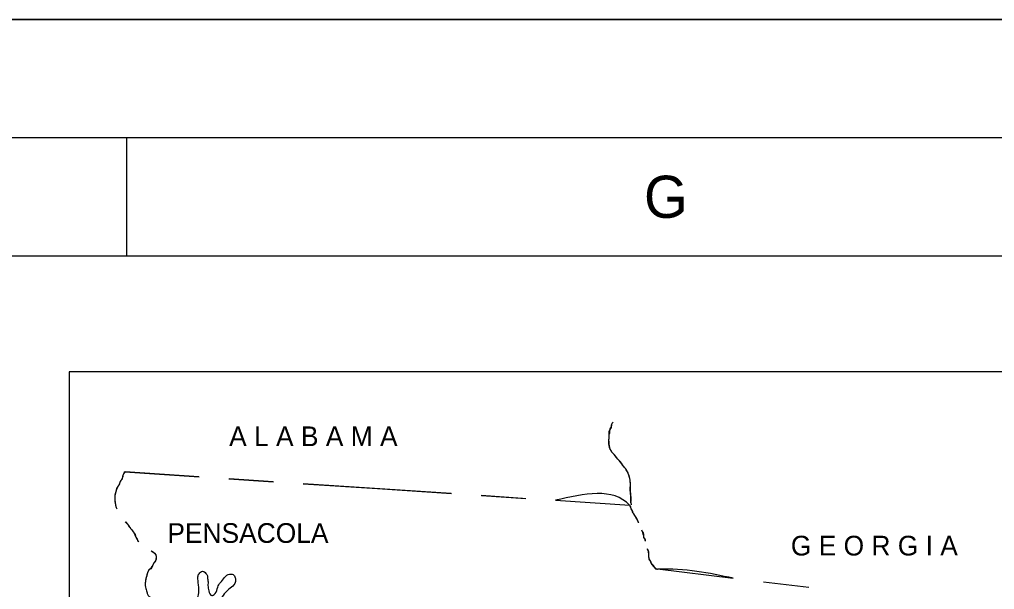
# Model space of a CAD drawing. Extents: x 492225 to 553725, y 1303773 to 1347273.
# Drawn here: x 534669 to 540852, y 1343657 to 1347273 of the extents above; entities that cross this region are included whole.
import ezdxf

# ---------------------------------------------------------------- set-up
doc = ezdxf.new("R2010")
doc.units = 0
for name, color, linetype in [('G-ANNO-TTLB', 7, 'Continuous'), ('Level 62', 7, 'Continuous'), ('Level 63', 7, 'Continuous')]:
    doc.layers.add(name, color=color, linetype=linetype)

msp = doc.modelspace()

# ---------------------------------------------------------------- linework, layer by layer
at = {"layer": 'G-ANNO-TTLB'}
for p, q in [((552975.069, 1346522.564), (492975.069, 1346522.564)), ((535350.069, 1345772.564), (535350.069, 1346522.564)), ((494850.069, 1345772.564), (552225.069, 1345772.564))]:
    msp.add_line(p, q, dxfattribs=at)
for points in [[(492225.069, 1303772.564), (553725.069, 1303772.564), (553725.069, 1347272.564), (492225.069, 1347272.564)], [(492225.069, 1303772.564), (553725.069, 1303772.564), (553725.069, 1347272.564), (492225.069, 1347272.564)], [(492225.069, 1347272.564), (553725.069, 1347272.564), (553725.069, 1303772.564), (492225.069, 1303772.564)]]:
    msp.add_lwpolyline(points, close=True, dxfattribs=at)
at = {"layer": 'Level 63'}
for p, q in [((535806.897, 1344371.438), (535338.382, 1344402.8405)), ((536277.1645, 1344340.028), (535999.0745, 1344359.173)), ((537406.5795, 1344266.3705), (536468.097, 1344327.7405)), ((537858.9745, 1344234.463), (537597.647, 1344253.413)), ((539674.507, 1343668.4205), (539386.667, 1343702.5305))]:
    msp.add_line(p, q, dxfattribs=at)
msp.add_lwpolyline([(534984.2995, 1333099.493), (548263.6245, 1333099.498), (548263.6245, 1345038.098), (534984.2995, 1345038.093)], close=True, dxfattribs=at)
for points in [[(535337.812, 1344402.5055), (535327.812, 1344391.2555), (535321.562, 1344372.5055), (535319.062, 1344357.5055), (535311.562, 1344347.5055), (535306.562, 1344342.5055), (535304.062, 1344330.0055), (535296.562, 1344315.0055), (535291.562, 1344310.0055), (535284.062, 1344291.2555), (535276.562, 1344263.7555), (535274.062, 1344248.7555), (535274.062, 1344216.2555), (535276.562, 1344201.2555), (535282.812, 1344177.5055), (535286.562, 1344167.5055)], [(535336.562, 1344402.5055), (535807.812, 1344371.2555)], [(535996.562, 1344358.7555), (536279.062, 1344340.0055)], [(536467.812, 1344327.5055), (536939.062, 1344297.5055)], [(536939.062, 1344297.5055), (537409.062, 1344266.2555)], [(537597.812, 1344253.7555), (537880.312, 1344235.0055)], [(538069.062, 1344222.5055), (538540.312, 1344191.2555)], [(538595.312, 1344078.7555), (538594.062, 1344081.2555), (538591.562, 1344088.7555), (538565.312, 1344136.2555), (538560.312, 1344141.2555), (538555.312, 1344156.2555), (538547.812, 1344168.7555), (538540.312, 1344191.2555)], [(535341.562, 1344085.0055), (535356.562, 1344070.0055), (535364.062, 1344055.0055), (535381.562, 1344035.0055), (535389.062, 1344022.5055), (535401.562, 1344005.0055), (535406.562, 1343988.7555), (535422.812, 1343960.0055)], [(538637.812, 1343962.5055), (538635.312, 1343977.5055), (538629.062, 1343987.5055), (538629.062, 1343997.5055), (538624.062, 1344007.5055), (538619.062, 1344025.0055), (538615.312, 1344033.7555)], [(535505.312, 1343902.5055), (535515.312, 1343896.2555), (535525.312, 1343886.2555), (535532.812, 1343876.2555), (535536.562, 1343858.7555), (535531.562, 1343838.7555), (535521.562, 1343826.2555), (535511.562, 1343807.5055), (535506.562, 1343800.0055), (535501.562, 1343790.0055), (535489.062, 1343780.0055), (535481.562, 1343765.0055), (535476.562, 1343745.0055), (535471.562, 1343732.5055), (535466.562, 1343698.7555), (535466.562, 1343681.2555)], [(538694.062, 1343801.2555), (538681.562, 1343816.2555), (538676.562, 1343821.2555), (538671.562, 1343833.7555), (538662.812, 1343848.7555), (538660.312, 1343866.2555), (538660.312, 1343878.7555), (538657.812, 1343897.5055), (538651.562, 1343915.0055)], [(539195.312, 1343727.5055), (538714.062, 1343785.0055)], [(539675.312, 1343668.7555), (539387.812, 1343703.7555)]]:
    msp.add_lwpolyline(points, dxfattribs=at)
msp.add_arc((538729.4504, 1343824.4208), 42.3255, 213.18290549, 248.62937772, dxfattribs=at)
for points in [[(538549.902, 1344195.138), (538546.1145, 1344214.0905), (538546.1145, 1344247.253), (538543.2745, 1344285.153), (538543.2745, 1344328.738), (538536.652, 1344372.0105), (538524.342, 1344403.2805), (538506.352, 1344429.8105), (538480.787, 1344463.9205), (538446.702, 1344504.663), (538420.1895, 1344537.8255), (538406.9745, 1344580.258), (538407.922, 1344631.423), (538412.657, 1344669.323), (538424.017, 1344689.223), (538424.017, 1344699.6455), (538433.487, 1344718.5955)], [(538550.312, 1344193.7555), (538547.812, 1344201.2555), (538547.812, 1344235.0055), (538542.812, 1344270.0055), (538542.812, 1344335.0055), (538537.812, 1344366.2555), (538526.562, 1344398.7555), (538506.562, 1344431.2555), (538499.062, 1344438.7555), (538484.062, 1344461.2555), (538466.562, 1344478.7555), (538444.062, 1344508.7555), (538427.812, 1344526.2555), (538412.812, 1344557.5055), (538407.812, 1344585.0055), (538407.812, 1344622.5055), (538410.312, 1344645.0055), (538412.812, 1344653.7555), (538415.312, 1344676.2555), (538422.812, 1344688.7555), (538425.312, 1344703.7555), (538432.812, 1344718.7555)], [(535338.382, 1344402.8405), (535329.5495, 1344394.278), (535324.082, 1344377.868), (535318.617, 1344358.0405), (535306.9995, 1344342.313), (535302.902, 1344326.588), (535297.4345, 1344316.3305), (535291.9695, 1344310.8605), (535281.037, 1344282.143), (535275.5695, 1344261.6305), (535272.837, 1344239.7505), (535274.887, 1344212.4005), (535279.6695, 1344185.733), (535282.402, 1344176.1605), (535285.8195, 1344169.323)], [(538596.1195, 1344078.7005), (538567.7145, 1344131.7605), (538562.032, 1344138.393), (538558.2445, 1344144.078), (538556.352, 1344153.5555), (538548.777, 1344168.7155), (538540.2545, 1344189.5605), (538539.417, 1344190.4805), (538068.4445, 1344222.593)], [(535339.7795, 1344085.743), (535356.1795, 1344070.018), (535366.427, 1344054.2905), (535381.4595, 1344035.1455), (535399.2245, 1344007.113), (535406.742, 1343989.3355), (535422.457, 1343961.3005)], [(538637.7345, 1343963.403), (538636.787, 1343975.7205), (538628.267, 1343987.093), (538629.212, 1343999.4105), (538614.0645, 1344031.6255)], [(535504.3045, 1343902.763), (535517.9695, 1343893.1905), (535530.952, 1343878.148), (535536.4195, 1343859.003), (535531.637, 1343838.4905), (535520.7045, 1343826.8655), (535501.572, 1343788.5755), (535489.957, 1343781.738), (535480.392, 1343763.2755), (535474.242, 1343737.978), (535468.092, 1343717.4655), (535467.4095, 1343703.1055)], [(539195.0545, 1343727.9855), (538715.307, 1343784.758), (538704.8895, 1343785.7055), (538694.4745, 1343801.813), (538679.327, 1343818.868), (538671.752, 1343829.2905), (538668.9095, 1343839.713), (538661.337, 1343856.768), (538660.3895, 1343878.5605), (538657.5495, 1343899.4055), (538651.867, 1343912.6705)], [(535466.562, 1343681.2555), (535470.312, 1343663.7555), (535475.312, 1343648.7555), (535477.812, 1343636.2555), (535485.312, 1343618.7555), (535492.812, 1343611.2555), (535505.312, 1343603.7555), (535527.812, 1343596.2555), (535540.312, 1343588.7555), (535542.812, 1343571.2555), (535542.812, 1343552.5055), (535532.812, 1343545.0055), (535520.312, 1343537.5055), (535505.312, 1343537.5055), (535474.062, 1343505.0055), (535464.062, 1343488.7555), (535446.562, 1343471.2555), (535426.562, 1343463.7555), (535419.062, 1343458.7555), (535406.562, 1343456.2555), (535376.562, 1343440.0055), (535366.562, 1343425.0055), (535364.062, 1343407.5055), (535364.062, 1343397.5055), (535381.562, 1343377.5055), (535394.062, 1343372.5055), (535409.062, 1343395.0055), (535434.062, 1343400.0055), (535444.062, 1343400.0055), (535461.562, 1343397.5055), (535474.062, 1343390.0055), (535494.062, 1343383.7555), (535506.562, 1343388.7555), (535516.562, 1343396.2555), (535526.562, 1343398.7555), (535539.062, 1343403.7555), (535571.562, 1343413.7555), (535591.562, 1343427.5055), (535619.062, 1343442.5055), (535631.562, 1343460.0055), (535639.062, 1343475.0055), (535651.562, 1343492.5055), (535666.562, 1343508.7555), (535684.062, 1343511.2555), (535696.562, 1343506.2555), (535704.062, 1343501.2555), (535719.062, 1343506.2555), (535726.562, 1343513.7555), (535734.062, 1343516.2555), (535749.062, 1343531.2555), (535789.062, 1343590.0055), (535804.062, 1343622.5055), (535804.062, 1343686.2555), (535800.312, 1343736.2555), (535802.812, 1343750.0055), (535812.812, 1343762.5055), (535817.812, 1343767.5055), (535830.312, 1343772.5055), (535845.312, 1343765.0055), (535861.562, 1343735.0055), (535861.562, 1343727.5055), (535864.062, 1343712.5055), (535864.062, 1343681.2555), (535869.062, 1343648.7555), (535889.062, 1343618.7555), (535896.562, 1343621.2555), (535909.062, 1343631.2555), (535926.562, 1343672.5055), (535941.562, 1343700.0055), (535949.062, 1343707.5055), (535976.562, 1343741.2555), (535991.562, 1343751.2555), (536009.062, 1343753.7555), (536024.062, 1343751.2555), (536036.562, 1343731.2555), (536039.062, 1343721.2555), (536034.062, 1343695.0055), (536005.312, 1343665.0055), (535942.812, 1343586.2555), (535932.812, 1343548.7555), (535925.312, 1343537.5055), (535905.312, 1343530.0055), (535890.312, 1343527.5055), (535840.312, 1343512.5055), (535827.812, 1343505.0055), (535795.312, 1343481.2555), (535797.812, 1343468.7555), (535812.812, 1343461.2555), (535832.812, 1343456.2555), (535842.812, 1343458.7555), (535867.812, 1343461.2555)]]:
    msp.add_spline(points, degree=3, dxfattribs=at)

# ---------------------------------------------------------------- texts
at = {"layer": 'G-ANNO-TTLB'}
msp.add_text('G', height=267.507, dxfattribs=at).set_placement((538629.069, 1346014.064))
at = {"layer": 'Level 62'}
for s, p in [('A L A B A M A ', (535998.3445, 1344566.2555)), ('PENSACOLA', (535606.562, 1343952.5055)), ('G E O R G I A', (539560.757, 1343872.5055))]:
    msp.add_text(s, height=125.0025, dxfattribs=at).set_placement(p)

doc.saveas('drawing.dxf')
